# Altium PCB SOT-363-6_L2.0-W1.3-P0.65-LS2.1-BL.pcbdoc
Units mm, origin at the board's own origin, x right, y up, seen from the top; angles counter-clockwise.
Board outline 15.2 x 15.54 mm, 2 copper layers (Top Layer, Bottom Layer), stack 0.07 mm thick; 1 components, 0 nets, 6 pads, 0 vias.
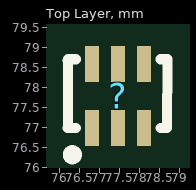
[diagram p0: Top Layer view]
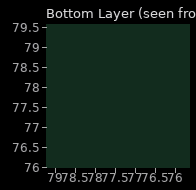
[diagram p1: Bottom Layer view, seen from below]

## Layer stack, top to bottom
Top Solder Mask Layer: solder mask 0.01, Dk 3.3
Top Layer: signal copper 0.035
Bottom Layer: signal copper 0.035
Bottom Solder Mask Layer: solder mask 0.01, Dk 3.3

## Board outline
85.048,69.85 69.85,69.85 69.85,85.393 85.048,85.393

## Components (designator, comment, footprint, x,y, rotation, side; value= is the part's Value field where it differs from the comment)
? "SOT-363-6_L2.0-W1.3-P0.65-LS2.1-BL" SOT-363-6_L2.0-W1.3-P0.65-LS2.1-BL 77.463,77.793 r0 top

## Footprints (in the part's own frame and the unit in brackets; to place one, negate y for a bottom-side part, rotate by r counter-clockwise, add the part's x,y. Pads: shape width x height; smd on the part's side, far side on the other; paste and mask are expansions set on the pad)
SOT-363-6_L2.0-W1.3-P0.65-LS2.1-BL [mm]
  rect 0.35x0.9 smd paste+0 mask+0.051: 1(-0.65,-0.8) 2(0,-0.8) 3(0.65,-0.8) 4(0.65,0.8) 5(0,0.8) 6(-0.65,0.8)
  silkscreen extent -1.26,-1.59 1.24,0.92

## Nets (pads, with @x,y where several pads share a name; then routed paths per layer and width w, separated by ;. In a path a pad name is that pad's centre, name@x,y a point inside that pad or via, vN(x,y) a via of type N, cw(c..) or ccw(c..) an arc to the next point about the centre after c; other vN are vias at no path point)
pads on no net: ?.1 ?.2 ?.3 ?.4 ?.5 ?.6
